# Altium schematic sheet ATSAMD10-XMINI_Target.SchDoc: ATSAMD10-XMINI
size A3; Organization: ATMEL Norway; Address1: Vestre Rosten 79; Address2: N-7075 TILLER; Address3: NORWAY; DocumentNumber: A09-2378; Revision: 2; SheetNumber: 2; SheetTotal: 3; PageSetup: Record=PageOptions¦CenterHorizontal=True¦CenterVertical=True¦PrintScale=1.01¦XCorrection=1.00¦YCorrection=1.00¦PrintKind=1¦BorderSize=5000000¦LeftOffset=0¦BottomOffset=0¦Orientation=2¦PaperLength=1000¦PaperWidth=1000¦Scale=100¦PaperSource=7¦PrintQuality=-4¦MediaType=1¦DitherType=10¦PaperKind=A3 (297 x 420 mm)¦PrintScaleMode=1
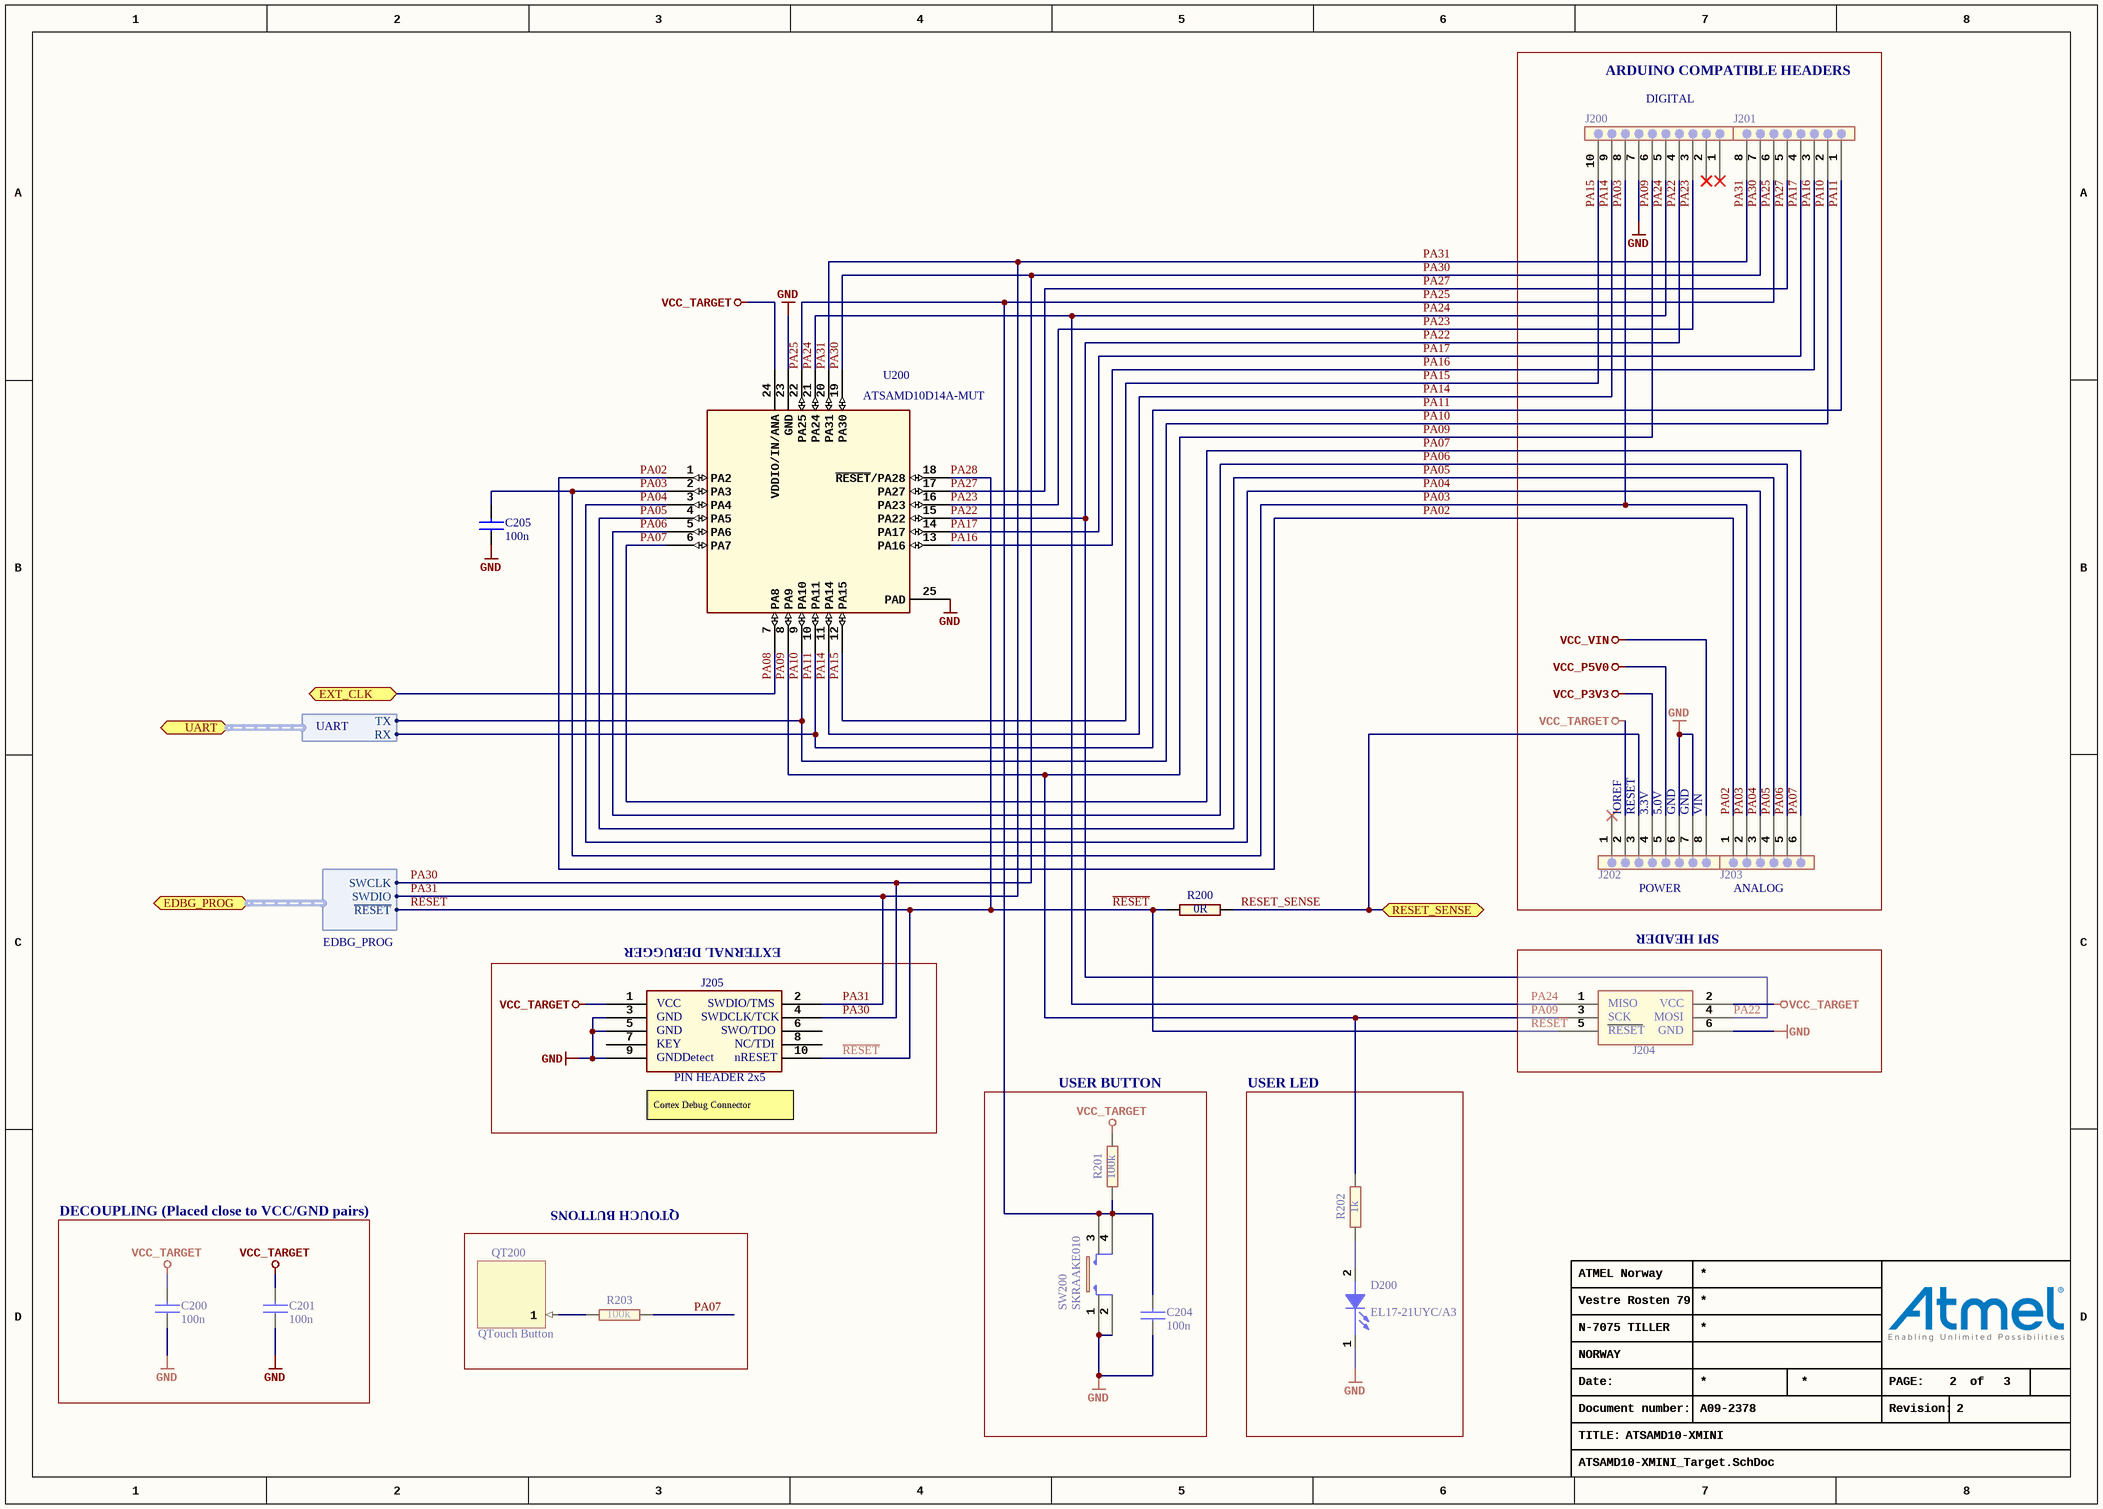
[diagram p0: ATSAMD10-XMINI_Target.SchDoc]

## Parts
C200  value 100n  [AP1-00001]
C201  value 100n  [AP1-00001]
C204  value 100n  [AP1-00001]
C205  value 100n  [AP1-00001]
D200  value EL17-21UYC/A3  [AP4-00013]
J200  (no value)  [AP8-00822]
J201  (no value)  [AP8-00823]
J202  (no value)  [AP8-00823]
J203  (no value)  [AP8-00824]
J204  (no value)  [AP8-00182]
J205  value PIN HEADER 2x5  [AP8-00257]
QT200  QTouch Button  (no BOM)
R200  value 0R  [AP2-00000]
R201  value 100k  [AP2-00000]
R202  value 1k  [AP2-00000]
R203  value 100k  [AP2-00000]
SW200  value SKRAAKE010  [AP8-00137]
U200  value ATSAMD10D14A-MUT  [AP6-00371]

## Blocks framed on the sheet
ARDUINO COMPATIBLE HEADERS: J200-J203
USER BUTTON: C204 R201 SW200
USER LED: D200 R202
DECOUPLING (Placed close to VCC/GND pairs): C200 C201

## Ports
EDBG_PROG (harness EDBG_PROG), EXT_CLK (bidir), RESET_SENSE, UART (harness UART)

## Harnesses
EDBG_PROG: ~{RESET}, SWDIO, SWCLK
UART: RX, TX

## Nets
GND: C200.1 C201.1 C204.1 C205.1 D200.1(CATHODE) J200.7 J202.6 J202.7 J204.6 J205.3 J205.5 J205.9 SW200.1 SW200.2 U200.23(GND) U200.25(PAD)
VCC_P3V3: J202.4
VCC_P5V0: J202.5
VCC_TARGET: C200.2 C201.2 J202.2 J204.2 J205.1 R201.2 U200.24(VDDIO/IN/ANA)
VCC_VIN: J202.8
PA02: J203.1 U200.1(PA2)
PA03: C205.2 J200.8 J203.2 U200.2(PA3)
PA04: J203.3 U200.3(PA4)
PA05: J203.4 U200.4(PA5)
PA06: J203.5 U200.5(PA6)
PA07: J203.6 R203.2 U200.6(PA7)
PA08: U200.7(PA8) ; port EXT_CLK
PA09: J200.6 J204.3 R202.2 U200.8(PA9)
PA10: J201.2 U200.9(PA10) ; port UART.TX
PA11: J201.1 U200.10(PA11) ; port UART.RX
PA14: J200.9 U200.11(PA14)
PA15: J200.10 U200.12(PA15)
PA16: J201.3 U200.13(PA16)
PA17: J201.4 U200.14(PA17)
PA22: J200.4 J204.4 U200.15(PA22)
PA23: J200.3 U200.16(PA23)
PA24: J200.5 J204.1 U200.21(PA24)
PA25: C204.2 J201.6 R201.1 SW200.3 SW200.4 U200.22(PA25)
PA27: J201.5 U200.17(PA27)
PA28: J204.5 J205.10 R200.1 U200.18(~{RESET}/PA28) ; port EDBG_PROG.~{RESET}  [also labelled ~{RESET}]
PA30: J201.7 J205.4 U200.19(PA30) ; port EDBG_PROG.SWCLK
PA31: J201.8 J205.2 U200.20(PA31) ; port EDBG_PROG.SWDIO
RESET_SENSE: J202.3 R200.2 ; port RESET_SENSE
NetD200_2: D200.2(ANODE) R202.1
NetQT200_1: QT200.1 R203.1

Not connected (* = marked no-connect by the designer): J200 1* 2*; J202 1*; J205 6 7 8

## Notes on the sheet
- (near J200) DIGITAL
- (near J202) IOREF
- (near J202) RESET
- (near J202) 3.3V
- (near J202) 5.0V
- (near J202) GND
- GND
- VIN
- (near J202) POWER
- ANALOG
- (near J205) EXTERNAL DEBUGGER
- SPI HEADER
- (near J205) Cortex Debug Connector
- QTOUCH BUTTONS
- Date:
- PAGE:
- of
- TITLE:
- Document number:
- Revision:

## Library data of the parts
C200 C201 C204 C205 = A01-0246: Ceramic capacitor, SMD 0402, X7R, 16V, +/-10%; PartGroup: Capacitors,Ceramic,SMD 0402; Manufacturer: Kemet; MPN: C0402C104K4RACTU; TemperatureRange: -55 - +125 deg C
D200 = A10-0019: LED, Yellow, Wave length=591nm, SMD 0805, ±70°; PartGroup: Opto,LEDs,SMD; Manufacturer: Everlight; MPN: 17-21UYC/S530-A3/TR8; TemperatureRange: -40 to +85 deg C
J200 = A08-2026: 1x10 receptacle pin header, low insertion force, 2.54mm pitch THM, Pin in Paste; PartGroup: Mechanical devices,Connectors,Pin header receptacle; Manufacturer: SAMTEC; Value: SSQ-110-21-F-S
J201 J202 = A08-2025: 1x8 receptacle pin header, low insertion force, 2.54mm pitch THM, Pin in Paste; PartGroup: Mechanical devices,Connectors,Pin header receptacle; Manufacturer: SAMTEC; Value: SSQ-108-21-F-S
J203 = A08-2024: 1x6 receptacle pin header, low insertion force, 2.54mm pitch THM; PartGroup: Mechanical devices,Connectors,Pin header receptacle; Manufacturer: SAMTEC; Value: SSQ-106-21-F-S
J204 = A08-0538: 2x3 pin header, 2.54 mm pitch, THM; PartGroup: Mechanical devices,Connectors,Pin headers; Manufacturer: SAMTEC; Value: MTSW-103-08-L-D-276; TemperatureRange: max. 125 degrees
J205 = A08-0385: 2x5 pin header, 1.27mm pitch, THM; PartGroup: Mechanical devices,Connectors,Pin headers; Manufacturer: Garry; MPN: 176-2-010-0-T-XS0-0730
QT200 = QTouchButton: ConfiguratorName: ATMEL_TOUCH; ConfigurationParameters: {}__sensorid[1]{}width[8]{}height[8]{}
R200 = A02-0163: RES 0.0 OHM 1/16W 0402 SMD; PartGroup: Resistors,SMD,0402 1%; Manufacturer: (n/a); MPN: RMCF0402ZT0R00; Tolerance: 1 %; TemperatureRange: -55 - +125 deg C
R201 R203 = A02-0260: Thick film resistor, SMD 0402, 1/16W, 1%; PartGroup: Resistors,SMD,0402 1%; Manufacturer: ASJ; MPN: CR10-1003-FK; TemperatureRange: -55ï¿½ to +125ï¿½C
R202 = A02-0212: Thick film resistor, SMD 0402, 1/16W, 1%; PartGroup: Resistors,SMD,0402 1%; Manufacturer: ASJ; MPN: CR10-1001-FK; TemperatureRange: -55 - +125 deg C
SW200 = A08-0790: 6.2x6.2 mm SMD tact switch, same as A08-0091 but less force is needed; PartGroup: Mechanical devices,Switches,SMD; Manufacturer: ALPS; TemperatureRange: -30 - +90 deg C
U200 = A06-1148: Atmel 32-bit RISC MCU; PartGroup: Integrated Circuits,MCU, MPU, DSP,ARM MCU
